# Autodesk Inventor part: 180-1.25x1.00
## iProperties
Created: 2007-06
Part Number: 180-1.25x1.00
Document SubType Name: Modeling
Designer: btaylor
Density: 1 g/cm^3
Author: btaylor
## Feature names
1. Extrusion1
2. Extrusion2
3. Extrusion3
4. Fillet1
5. Extrusion4
6. Fillet2
7. Fillet3
8. Fillet4
9. Extrusion5
10. Extrusion6
11. Fillet5
12. Chamfer1
13. Chamfer2
